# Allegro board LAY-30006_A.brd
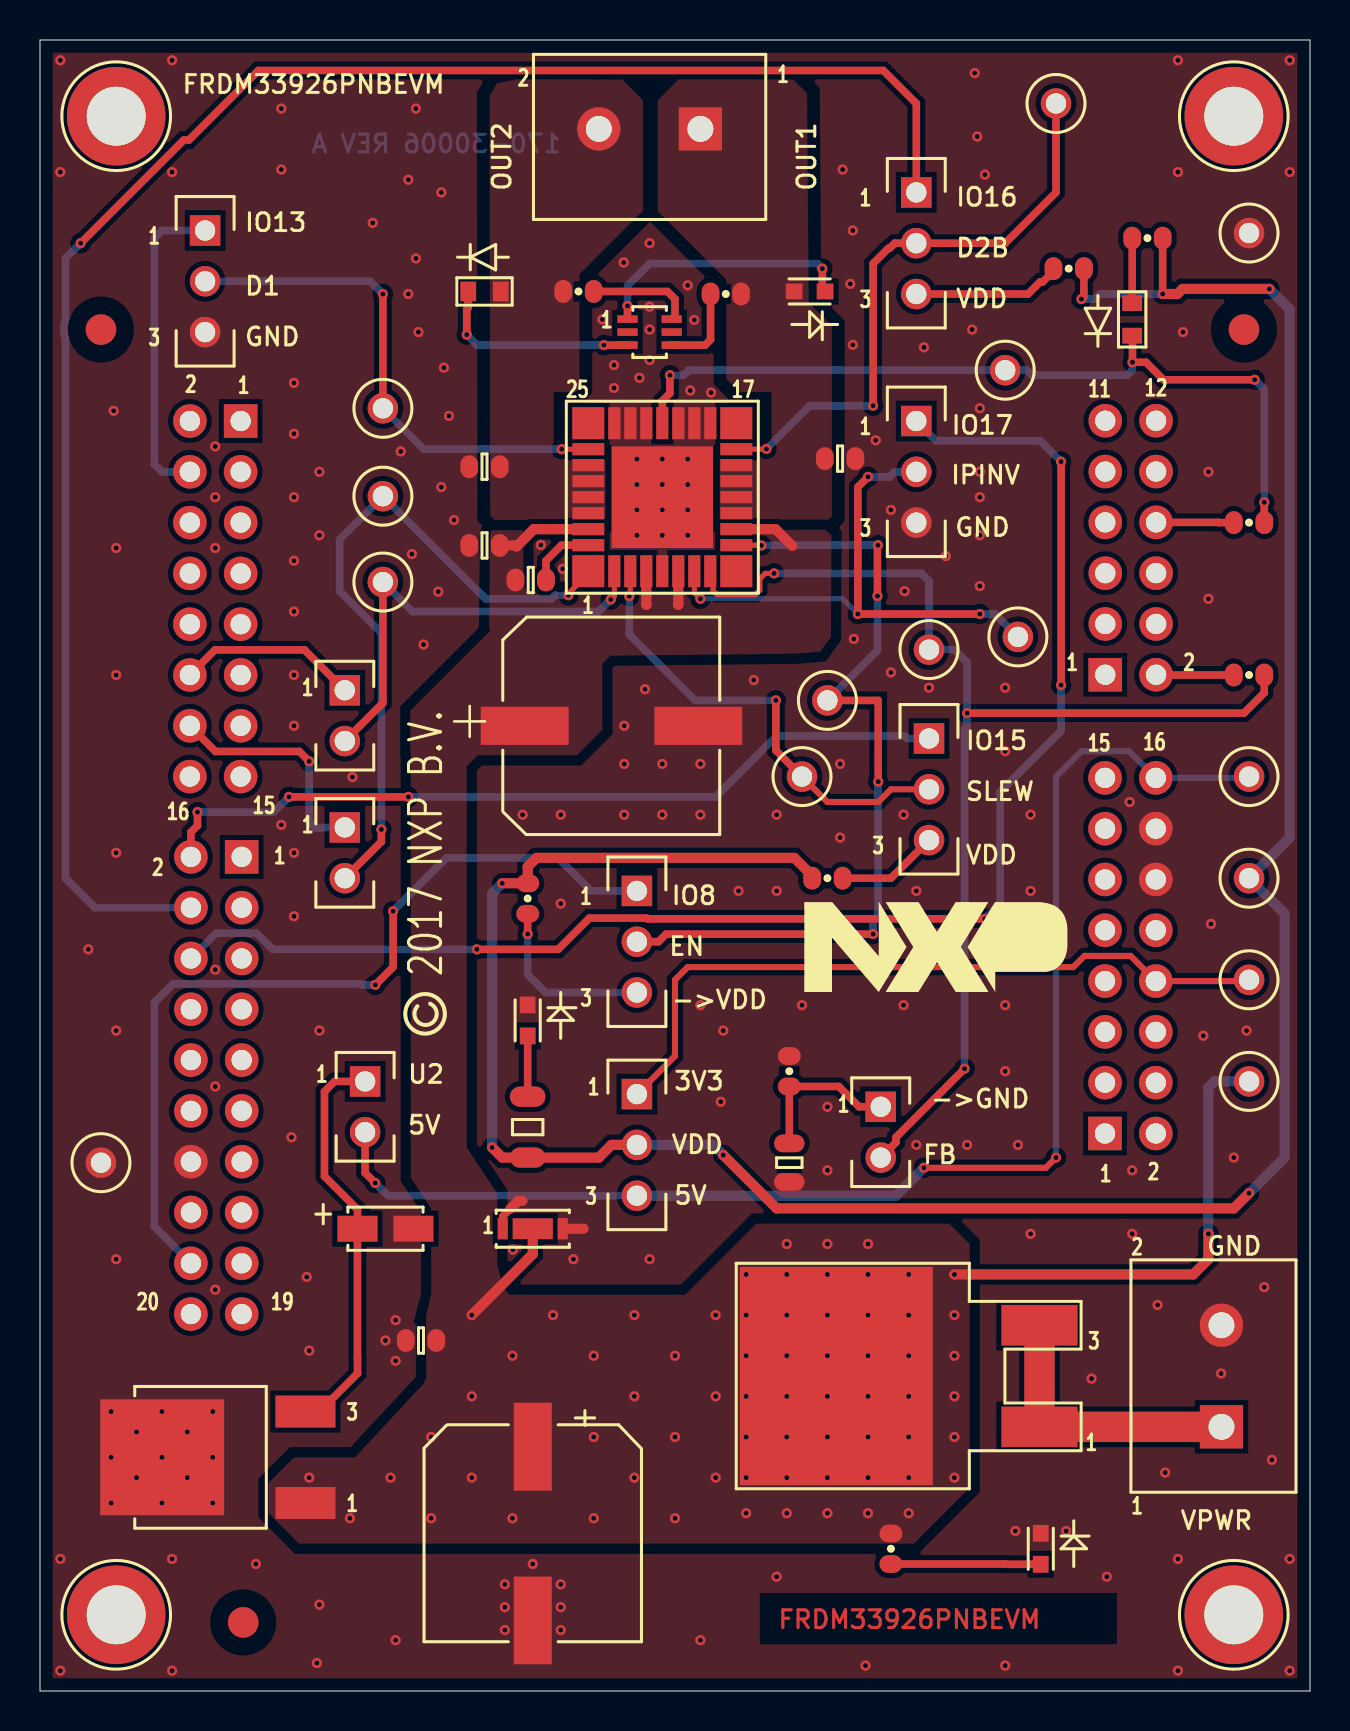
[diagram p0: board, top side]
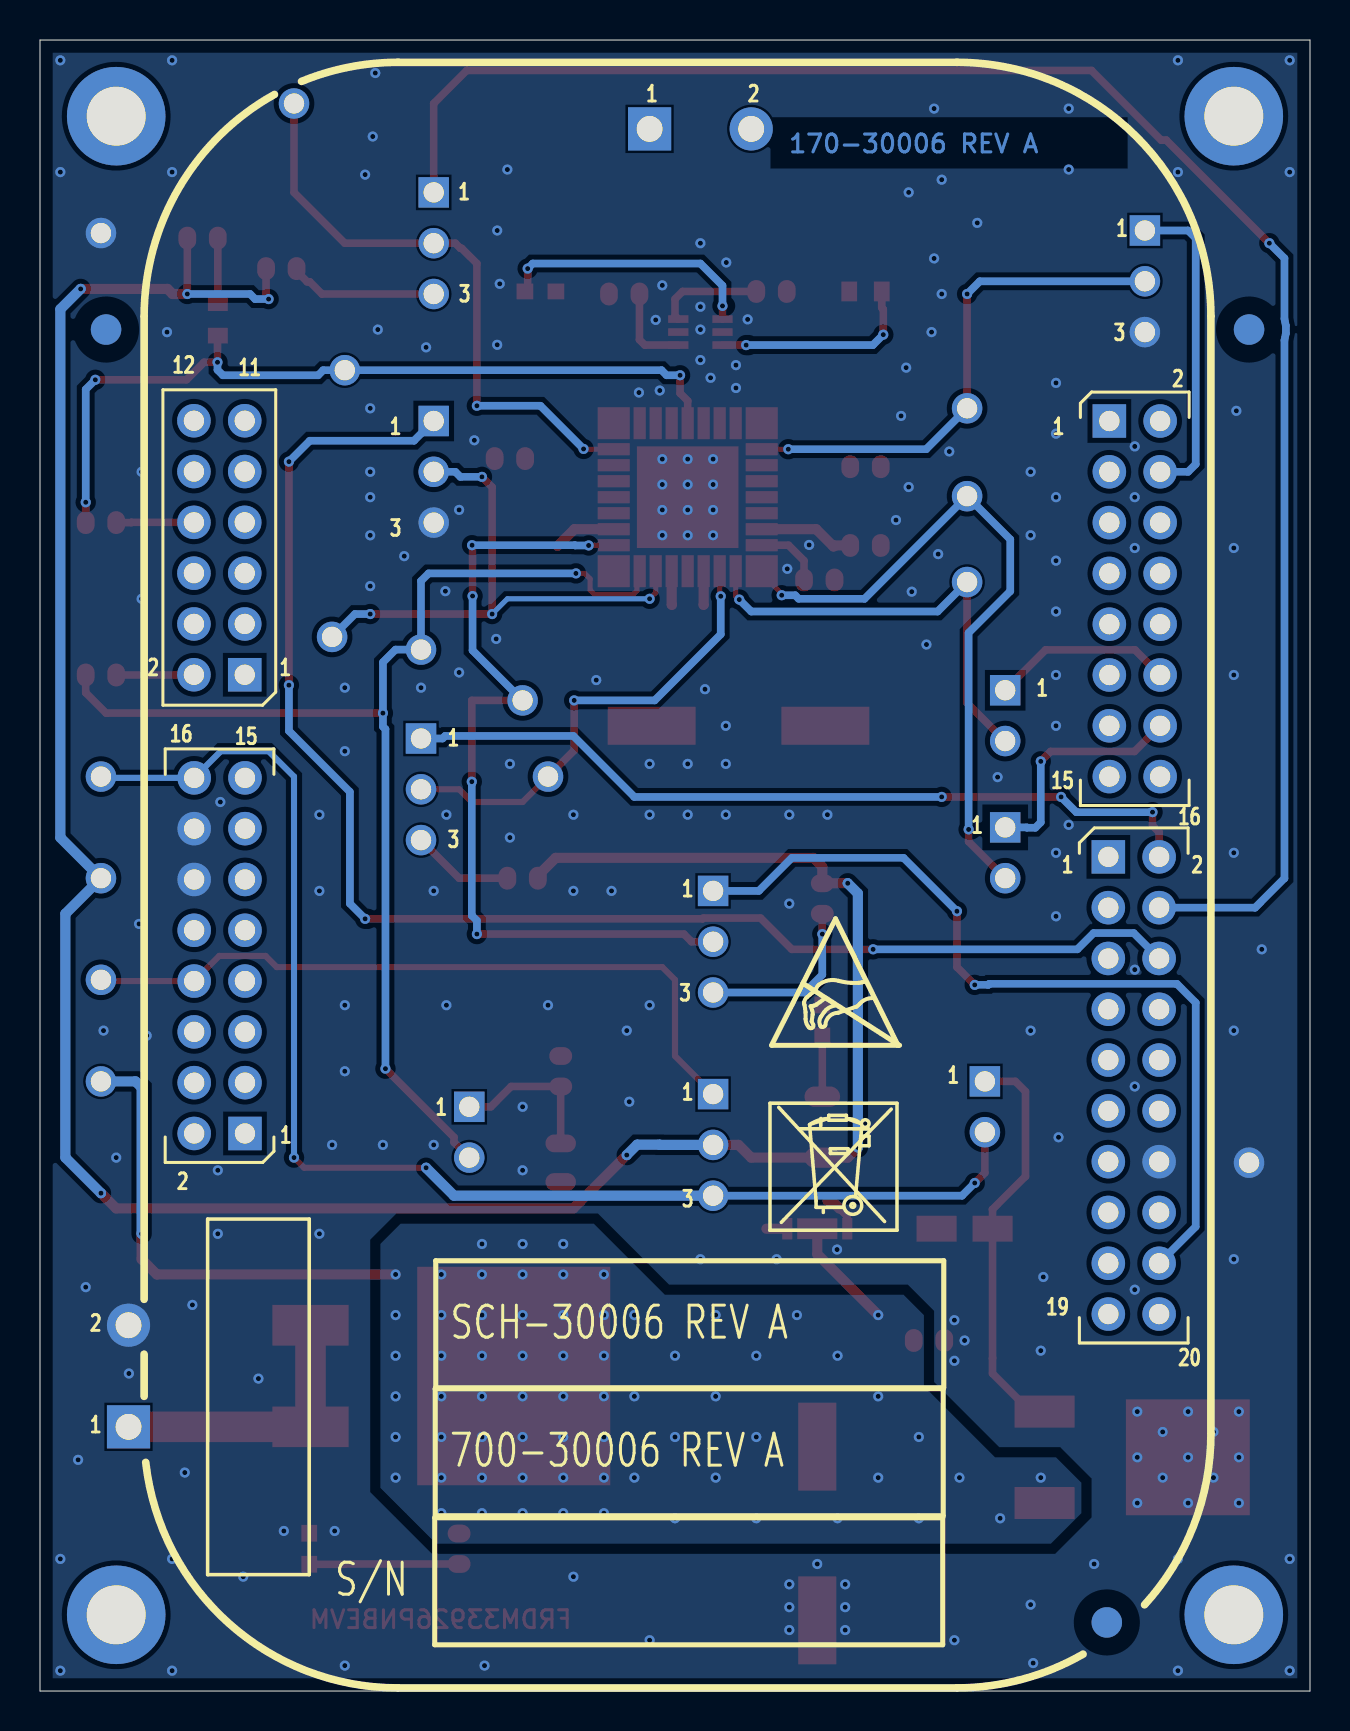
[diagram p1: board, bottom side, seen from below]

Outline 63.5 x 82.55 mm; copper layers: TOP, L2_GND, L3_PWR, BOTTOM. Coordinates in mm from the lower left corner of the outline.
Outline path: 0,82.55 0,0 63.5,0 63.5,82.55 0,82.55

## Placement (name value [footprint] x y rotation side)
BH1  SMTSO-M1.6-2.25ET  [MH194-116T]  3.81 3.81 0 top
BH2  SMTSO-M1.6-2.25ET  [MH194-116T]  59.69 3.81 0 top
BH3  SMTSO-M1.6-2.25ET  [MH194-116T]  59.69 78.74 0 top
BH4  SMTSO-M1.6-2.25ET  [MH194-116T]  3.81 78.74 0 top
C1  47uF  [CCE10_3X10_3]  24.64 7.87 270 top
C2  0.1uF  [CC0603_OV]  19.05 17.53 180 top
C3  10UF  [CASE_A]  17.27 23.11 0 top
C4  47uF  [CCE10_3X10_3]  28.57 48.26 0 top
C5  0.1uF  [CC0603_OV]  22.22 57.28 180 top
C6  0.047UF  [CC0805_OV]  37.47 26.42 270 top
C7  0.033UF  [CC0603_OV]  24.54 55.55 180 top
C8  10nF  [CC0603_OV]  40.01 61.62 0 top
C9  10nF  [CC0603_OV]  22.22 61.21 180 top
D1  MBRB1045T4G  [D2PAK_B]  43.28 15.75 90 top
D2  SPT02-236DDB  [DIODE3_UQFN_SM]  24.64 23.11 0 top
D2B1  TEST POINT BLUE  [TEST_LOOP]  50.8 79.38 0 top
D3  LED_YEL  [LED_0603]  50.04 7.11 90 top
D4  LED GREEN  [LED_0603]  24.38 33.53 90 top
D5  RED  [0603LED]  54.61 68.58 270 top
D6  LED GREEN  [LED_0603]  38.48 69.98 0 top
D7  RED  [0603LED]  22.22 69.98 180 top
D8  BAS70TW-7-F  [SC70-6]  30.48 67.95 270 top
EN1  TEST POINT WHITE  [TEST_LOOP]  39.37 49.53 0 top
FB1  TEST POINT ORANGE  [TEST_LOOP]  44.45 52.07 0 top
GND1  TEST POINT BLACK  [TEST_LOOP]  60.45 72.9 0 top
GND2  TEST POINT BLACK  [TEST_LOOP]  3.05 26.42 0 top
IN1  TEST POINT BLUE  [TEST_LOOP]  17.14 55.45 0 top
IN2  TEST POINT BLUE  [TEST_LOOP]  17.14 59.74 0 top
INPINV1  TEST POINT BLUE  [TEST_LOOP]  48.9 52.71 0 top
J1  HDR_2X8  [HDR208]  10.03 63.5 180 bottom
J2  HDR_2x10  [HDR210]  10.08 41.71 180 bottom
J3  HDR 2X6 TH  [HDR206]  53.26 50.81 0 bottom
J4  HDR_2X8  [HDR208]  53.25 27.88 0 bottom
J5  OSTTC022162  [CON2_TB_5P08_TH_OSTTC]  59.07 13.21 90 top
J6  OSTTC022162  [CON2_TB_5P08_TH_OSTTC]  33.02 78.11 180 top
JP1  HDR 1X2  [HDR102]  16.26 30.48 0 top
JP2  HDR 1X3  [HDR103]  29.84 29.84 0 top
JP3  HDR 1X2  [HDR102]  42.04 29.21 0 top
JP4  HDR 1X3  [HDR103]  8.26 73.03 0 top
JP5  HDR 1X3  [HDR103]  29.84 40.01 0 top
JP6  HDR 1X2  [HDR102]  15.24 50.04 0 top
JP7  HDR 1X2  [HDR102]  15.24 43.18 0 top
JP8  HDR 1X3  [HDR103]  43.82 74.93 0 top
JP9  HDR 1X3  [HDR103]  44.45 47.62 0 top
JP10  HDR 1X3  [HDR103]  43.82 63.5 0 top
NOREF  -  [unnamed]  3.05 68.07 0 top
NOREF#2  -  [#2]  -97.43 -69.06 0 top
NOREF#3  -  [#2]  0 82.55 0 top
NOREF#4  -  [#2]  27.41 55.99 90 top
NOREF#5  -  [#2]  38.23 34.95 0 top
NOREF#6  -  [unnamed]  60.2 68.07 0 top
NOREF#7  -  [unnamed]  10.16 3.43 0 top
NOREF#8  -  [#2]  -361.54 258.75 0 top
NOREF#9  -  [#2]  63.5 0 90 top
NOREF#10  -  [#2]  27.41 55.99 0 top
NOREF#11  -  [#2]  -17.86 -36.68 0 top
NOREF#12  -  [#2]  -402.67 -260.83 0 top
NOREF#13  -  [#2]  3.81 3.81 0 top
NOREF#14  -  [#2]  50.04 5.82 0 top
NOREF#15  -  [#2]  19.28 33.86 90 top
NOREF#16  -  [#2]  116.92 82.58 0 top
NOREF#17  -  [#2]  26.29 22.36 90 top
NOREF#18  -  [#2]  22.99 22.36 0 top
NOREF#19  -  [#2]  23.14 23.11 0 top
NOREF#20  -  [unnamed]  10.16 3.43 180 bottom
NOREF#21  -  [#2]  27 23.04 180 bottom
NOREF#22  -  [unnamed]  3.05 68.07 180 bottom
NOREF#23  -  [#2]  43.71 15.16 180 bottom
NOREF#24  -  [#2]  43.76 2.31 180 bottom
NOREF#25  -  [#2]  26.9 32.28 180 bottom
NOREF#26  -  [unnamed]  60.2 68.07 180 bottom
NOREF#27  -  [#2]  50.04 5.82 90 bottom
NOREF#28  -  [#2]  43.74 8.76 180 bottom
R1  1K  [RC0603_OV]  42.55 7.11 270 top
R2  470  [RC1206_OV]  24.38 28.19 90 top
R3  4.70K  [RC0603_OV]  55.37 72.64 180 top
R4  270  [RC0603_OV]  37.47 30.99 90 top
R5  0  [RC0603_OV]  60.45 58.42 0 top
R6  0  [RC0603_OV]  60.45 50.8 0 top
R7  1K  [RC0603_OV]  24.38 39.62 270 top
R8  10.0K  [RC0603_OV]  26.92 69.98 180 top
R9  10.0K  [RC0603_OV]  34.29 69.85 0 top
R10  1K  [RC0603_OV]  51.44 71.12 180 top
R11  1K  [RC0603_OV]  39.37 40.64 0 top
SF_B1  TEST POINT YELLOW  [TEST_LOOP]  48.26 66.04 0 top
SLEWSEL1  TEST POINT BLUE  [TEST_LOOP]  38.1 45.72 0 top
TP_D1  TEST POINT WHITE  [TEST_LOOP]  17.14 64.14 0 top
U2  MC78M05CDTRKG  [DPAK_CASE_369C-01]  7.39 11.68 90 top
U3  MC33926  [PQFN32_0P8_8X8_SLUG]  31.11 59.69 90 top
UNK3V3  TEST POINT RED  [TEST_LOOP]  60.45 35.56 0 top
UNK5V0  TEST POINT RED  [TEST_LOOP]  60.45 45.72 0 top
VDD1  TEST POINT RED  [TEST_LOOP]  60.45 40.64 0 top
VPWR1  TEST POINT RED  [TEST_LOOP]  60.45 30.48 0 top

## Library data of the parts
BH1-BH4 = MOUNT_HOLE
C1 C3 C4 = CAP_POL
C2 C5-C9 = CAP_NP
D1 = Diode_13A_4C
D2 = DZ_DUAL_CK_A1A2C
D2B1 EN1 FB1 GND1 GND2 IN1 IN2 INPINV1 SF_B1 SLEWSEL1 TP_D1 UNK3V3 UNK5V0 VDD1 VPWR1 = TestLoop
D3-D7 = LED
D8 = BAS70TW
J1 J4 = CONN_HDR_8X2
J2 = CONN_HDR_10X2
J3 = CONN_HDR_6X2
J5 J6 = HDR-1X2
JP1 JP3 JP6 JP7 = CONN_HDR_2X1
JP2 JP4 JP5 JP8-JP10 = CONN_HDR_3X1
R1-R11 = RES
U2 = MC7805
U3 = MC33926

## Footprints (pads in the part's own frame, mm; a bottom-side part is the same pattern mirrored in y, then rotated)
0603LED
  rect 0.787x0.991 smd: A(-0.813,0) C(0.813,0)
CASE_A
  rect 2.007x1.295 smd: 1(-1.4,0) 2(1.4,0)
CC0603_OV
  oval 0.889x1.143 smd: 1(-0.762,0) 2(0.762,0)
CC0805_OV
  oval 0.889x1.524 smd: 1(-0.965,0) 2(0.965,0)
CCE10_3X10_3
  rect 4.394x1.905 smd: 1(-4.343,0) 2(4.343,0)
CON2_TB_5P08_TH_OSTTC
  rect 2.159x2.159 hole 1.295: 1(0,0)
  round 2.159 hole 1.295: 2(5.08,0)
D2PAK_B
  rect 2.032x3.81 smd: 1(-2.54,-6.695) 3(2.54,-6.695)
  rect 10.922x9.652 smd: 4(0,3.465)
DIODE3_UQFN_SM
  rect 0.508x1.067 smd: 1(-1.5,0) 2(1.5,0)
  rect 2.007x1.041 smd: 3(0,0)
DPAK_CASE_369C-01
  rect 1.6x2.997 smd: 1(-2.286,-5.88) 3(2.286,-5.88)
  rect 5.791x6.198 smd: 4(0,1.283)
HDR102
  rect 1.524x1.524 hole 1.016: 1(0,0)
  round 1.524 hole 1.016: 2(0,-2.54)
HDR103
  rect 1.524x1.524 hole 1.016: 1(0,0)
  round 1.524 hole 1.016: 2(0,-2.54) 3(0,-5.08)
HDR206
  rect 1.676x1.676 hole 1.016: 1(0,0)
  round 1.676 hole 1.016: 2(2.54,0) 3(0,-2.54) 4(2.54,-2.54) 5(0,-5.08) 6(2.54,-5.08) 7(0,-7.62) 8(2.54,-7.62) 9(0,-10.16) 10(2.54,-10.16) 11(0,-12.7) 12(2.54,-12.7)
HDR208
  rect 1.676x1.676 hole 1.016: 1(0,0)
  round 1.676 hole 1.016: 2(2.54,0) 3(0,-2.54) 4(2.54,-2.54) 5(0,-5.08) 6(2.54,-5.08) 7(0,-7.62) 8(2.54,-7.62) 9(0,-10.16) 10(2.54,-10.16) 11(0,-12.7) 12(2.54,-12.7) 13(0,-15.24) 14(2.54,-15.24) 15(0,-17.78) 16(2.54,-17.78)
HDR210
  rect 1.676x1.676 hole 1.016: 1(0,0)
  round 1.676 hole 1.016: 2(2.54,0) 3(0,-2.54) 4(2.54,-2.54) 5(0,-5.08) 6(2.54,-5.08) 7(0,-7.62) 8(2.54,-7.62) 9(0,-10.16) 10(2.54,-10.16) 11(0,-12.7) 12(2.54,-12.7) 13(0,-15.24) 14(2.54,-15.24) 15(0,-17.78) 16(2.54,-17.78) 17(0,-20.32) 18(2.54,-20.32) 19(0,-22.86) 20(2.54,-22.86)
LED_0603
  rect 0.838x0.787 smd: A(-0.775,0) C(0.775,0)
MH194-116T
  round 4.928 hole 2.946: 1(0,0)
PQFN32_0P8_8X8_SLUG
  rect 1.6x1.6 smd: 1(-3.7,3.7) 9(-3.7,-3.7) 17(3.7,-3.7) 25(3.7,3.7)
  rect 1.6x0.61 smd: 2(-3.7,2.4) 3(-3.7,1.6) 4(-3.7,0.8) 5(-3.7,0) 6(-3.7,-0.8) 7(-3.7,-1.6) 8(-3.7,-2.4) 18(3.7,-2.4) 19(3.7,-1.6) 20(3.7,-0.8) 21(3.7,0) 22(3.7,0.8) 23(3.7,1.6) 24(3.7,2.4)
  rect 0.61x1.6 smd: 10(-2.4,-3.7) 11(-1.6,-3.7) 12(-0.8,-3.7) 13(0,-3.7) 14(0.8,-3.7) 15(1.6,-3.7) 16(2.4,-3.7) 26(2.4,3.7) 27(1.6,3.7) 28(0.8,3.7) 29(0,3.7) 30(-0.8,3.7) 31(-1.6,3.7) 32(-2.4,3.7)
  rect 5.08x5.08 smd: 33(0,0)
RC0603_OV
  oval 0.889x1.143 smd: 1(-0.762,0) 2(0.762,0)
RC1206_OV
  oval 1.016x1.778 smd: 1(-1.524,0) 2(1.524,0)
SC70-6
  rect 0.381x1.016 smd: 1(-0.65,-1.105) 2(0,-1.105) 3(0.65,-1.105) 4(0.65,1.105) 5(0,1.105) 6(-0.65,1.105)
TEST_LOOP
  round 1.524 hole 1.016: 1(0,0)
unnamed
  round 1.524 smd: (0,0)

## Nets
3V3: J4.8(B4) JP2.1 UNK3V3.1
5V: J4.16(B8) JP1.2 JP2.3 UNK5V0.1
GND_SIGNAL: C1.2 C2.2 C3.2 C4.2 C5.2 C6.2 C8.2 C9.2 D2.1(ANODE1) D2.2(ANODE2) D3.C(CATHODE) D4.C(CATHODE) GND1.1(PIN1) GND2.1(PIN1) J2.14 J4.12(B6) J4.14(B7) J5.2 JP4.3 JP10.3 R4.2 U2.4(GND) U3.5(AGND_1) U3.18(PGND_1) U3.19(PGND_2) U3.20(PGND_3) U3.22(PGND_4) U3.23(PGND_5) U3.24(PGND_6) U3.33(AGND_2)
VBAT: C1.1 C2.1 C4.1 C5.1 C7.2 D1.4(CATHODE) D2.3(CATHODE) R1.1 U2.1(IN) U3.4(VPWR_1) U3.6(VPWR_2) U3.11(VPWR_3) U3.31(VPWR_4) VPWR1.1(PIN1)
VDD: JP2.2 R2.1 R3.1 R7.1 R10.1 R11.1 VDD1.1(PIN1)
AN0: J3.2(B1) R6.1
D1: JP4.2 TP_D1.1(PIN1) U3.26(D1)
D2B: D2B1.1(PIN1) JP8.2 U3.16(D\2\)
EN: EN1.1(PIN1) JP5.2 U3.10(EN)
FB: FB1.1(PIN1) JP3.2 R6.2 U3.8(FB)
IN1: IN1.1(PIN1) JP6.2 U3.2(IN1)
IN2: IN2.1(PIN1) JP7.2 U3.1(IN2)
INPINV: INPINV1.1(PIN1) JP10.2 U3.7(INV)
IO8: J2.18 JP5.1
IO13: J1.4(B2) JP4.1
IO14: J3.8(B4) R5.1
IO15: J2.2 JP9.1
IO16: J2.4 JP8.1
IO17: J2.6 JP10.1
OUT1: C8.1 D6.A(ANODE) J6.1 R9.2 U3.12(OUT1_1) U3.13(OUT1_2) U3.14(OUT1_3) U3.15(OUT1_4)
OUT2: C9.1 D7.A(ANODE) J6.2 R8.2 U3.27(OUT2_1) U3.28(OUT2_2) U3.29(OUT2_3) U3.30(OUT2_4)
PWM1: J1.12(B6) JP6.1
PWM2: J1.14(B7) JP7.1
SF_B: D5.C(CATHODE) R5.2 SF_B1.1(PIN1) U3.21(S\F\)
SLEWSEL: JP9.2 SLEWSEL1.1(PIN1) U3.3(SLEW)
N16404454: D3.A(ANODE) R1.2
N16404466: D1.1(ANODE1) D1.3(ANODE2) J5.1
N16404596: C3.1 JP1.1 U2.3(OUT)
N16404846: JP5.3 R7.2
N16404992: C6.1 JP3.1 R4.1
N16405180: D7.C(CATHODE) D8.3(A3)
N16405200: D6.C(CATHODE) D8.1(A1)
N16405574: D4.A(ANODE) R2.2
N16406148: D8.4(C3) R9.1
N16406152: D8.6(C1) R8.1
N16409368: D5.A(ANODE) R3.2
N16478318: JP8.3 R10.2
N16492232: C7.1 U3.32(CCP)
N16695009: JP9.3 R11.2

Pads without a net: BH1 1; BH2 1; BH3 1; BH4 1; D8 2 5; J1 1 2 3 5 6 7 8 9 10 11 13 15 16; J2 1 3 5 7 8 9 10 11 12 13 15 16 17 19 20; J3 1 3 4 5 6 7 9 10 11 12; J4 1 2 3 4 5 6 7 9 10 11 13 15; U3 9 17 25

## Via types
v1: diameter 0.508, hole 0.254, TOP to BOTTOM, 319 vias

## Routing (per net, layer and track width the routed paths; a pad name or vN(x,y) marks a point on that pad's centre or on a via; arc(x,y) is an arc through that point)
3V3: length 36.2
  TOP w0.305: JP2.1 31.75,31.75 31.75,35.56 32.38,36.2 51.66,36.2 52.22,36.75 54.53,36.75 J4.8 60.39,35.5 UNK3V3.1
5V: length 67.6
  TOP w0.305: v1(44.2,26.16) 50.29,26.16 v1(50.8,26.67)
  TOP w0.381: JP1.2 16.26,25.91 v1(16.76,25.4)
  BOTTOM w0.305: v1(50.8,26.67) 50.8,45.72 52.07,46.99 54.46,46.99 J4.16 59.98,45.66 60.05,45.72 UNK5V0.1
  BOTTOM w0.381: JP2.3 17.4,24.76 v1(16.76,25.4)
  BOTTOM w0.508: JP2.3 42.8,24.76 v1(44.2,26.16)
GND_SIGNAL: length 3
  TOP w0.381: D2.1 23.14,23.73 23.52,24.12
  TOP w0.508: 24.13,24.51 23.92,24.51 23.52,24.12 ; D2.2 27.18,23.11
  vias: v1(1.02,81.53) v1(1.02,75.95) v1(1.02,6.6) v1(1.02,1.02) v1(2.41,37.08) v1(3.56,13.97) v1(3.56,11.68) v1(3.56,9.4) v1(3.68,64.01) v1(3.81,57.15) v1(3.81,50.8) v1(3.81,41.91) v1(3.81,33.02) v1(3.81,21.59) v1(4.83,12.95) v1(4.83,10.67) v1(6.1,13.97) v1(6.1,11.68) v1(6.1,9.4) v1(6.6,81.53) v1(6.6,75.95) v1(6.6,6.6) v1(6.6,1.02) v1(7.37,12.95) v1(7.37,10.67) v1(8.64,13.97) v1(8.64,11.68) v1(8.64,9.4) v1(8.76,62.23) v1(8.76,59.69) v1(8.76,57.15) v1(8.76,36.07) v1(8.76,30.23) v1(8.76,20.07) v1(10.79,6.35) v1(12.07,79.12) v1(12.07,76.07) v1(12.07,43.31) v1(12.57,27.69) v1(12.7,65.41) v1(12.7,62.87) v1(12.7,59.69) v1(12.7,56.52) v1(12.7,53.98) v1(12.7,50.8) v1(12.7,48.26) v1(12.7,41.91) v1(12.7,38.73) v1(13.34,20.7) v1(13.46,17.02) v1(13.84,1.4) v1(13.97,60.96) v1(13.97,57.79) v1(13.97,33.02) v1(13.97,4.32) v1(15.62,45.69) v1(16.64,73.41) v1(17.27,17.53) v1(17.78,18.54) v1(17.78,16.51) v1(17.78,2.54) v1(18.03,61.98) v1(18.41,75.56) v1(18.41,69.85) v1(18.59,56.85) v1(18.8,79.12) v1(18.8,71.63) v1(18.92,67.95) v1(19.18,52.32) v1(19.91,54.97) v1(20.07,74.93) v1(20.07,60.2) v1(20.19,66.17) v1(20.45,63.75) v1(20.7,58.55) v1(23.24,5.33) v1(23.24,4.19) v1(23.24,3.05) v1(23.65,22.07) v1(24.13,43.82) v1(24.64,6.35) v1(25.04,57.3) v1(26.04,43.82) v1(26.04,39.37) v1(26.04,5.33) v1(26.04,4.19) v1(26.04,3.05) v1(26.14,56.11) v1(26.67,21.59) v1(28.12,68.58) v1(28.7,66.29) v1(28.7,65.15) v1(29.18,71.42) v1(29.21,48.26) v1(29.21,46.36) v1(29.21,43.82) v1(29.84,61.59) v1(29.84,60.33) v1(29.84,59.05) v1(29.84,57.79) v1(29.97,65.66) v1(30.25,50.09) v1(30.48,72.39) v1(30.48,69.22) v1(30.48,68.07) v1(30.48,66.55) v1(30.48,21.59) v1(31.11,61.59) v1(31.11,60.33) v1(31.11,59.05) v1(31.11,57.79) v1(31.11,46.36) v1(31.11,43.82) v1(32.38,70.28) v1(32.38,61.59) v1(32.38,60.33) v1(32.38,59.05) v1(32.38,57.79) v1(32.51,65.02) v1(32.72,68.55) v1(33.02,46.36) v1(33.02,43.82) v1(33.02,34.29) v1(33.02,2.54) v1(33.55,64.92) v1(34.04,29.46) v1(34.16,33.02) v1(34.92,40.01) v1(35.69,50.55) v1(36.83,43.82) v1(36.83,40.01) v1(36.83,5.71) v1(38.1,34.29) v1(39.37,29.21) v1(39.37,26.04) v1(40.01,46.36) v1(40.01,42.67) v1(40.13,76.07) v1(40.51,70.36) v1(40.64,73.03) v1(40.64,67.31) v1(40.69,52.6) v1(41.28,1.27) v1(41.78,62.53) v1(42.55,59.05) v1(42.55,50.93) v1(43.23,54.99) v1(43.18,43.82) v1(43.18,34.29) v1(43.82,40.01) v1(43.82,27.3) v1(44.2,67.18) v1(44.45,50.16) v1(45.29,56.74) v1(46.36,27.3) v1(46.61,68.07) v1(46.74,80.9) v1(46.86,77.72) v1(46.99,64.14) v1(46.99,60.96) v1(46.99,59.69) v1(46.99,57.79) v1(46.99,55.25) v1(47.24,75.82) v1(48.26,50.16) v1(48.26,46.99) v1(48.26,34.29) v1(48.26,30.99) v1(48.26,1.27) v1(48.77,8) v1(48.9,27.3) v1(49.53,43.82) v1(49.53,40.01) v1(49.53,22.86) v1(51.31,8) v1(52.58,15.62) v1(53.34,5.71) v1(54.48,44.45) v1(54.61,26.04) v1(54.61,22.86) v1(55.88,19.3) v1(56.26,10.92) v1(56.9,81.53) v1(56.9,75.95) v1(56.9,6.6) v1(56.9,1.02) v1(57.15,67.95) v1(58.17,32.77) v1(58.42,60.96) v1(58.42,54.61) v1(58.55,38.35) v1(59.05,15.88) v1(59.69,26.67) v1(60.33,33.02) v1(61.21,20.19) v1(61.59,11.56) v1(62.48,81.53) v1(62.48,75.95) v1(62.48,6.6) v1(62.48,1.02)
VBAT: length 40.7
  TOP w0.508: 31.9,54.31 31.92,54.32 U3.6 ; U3.31 24.69,58.09 23.83,57.23 23.77,57.28 C5.1 ; v1(21.59,18.8) 24.64,21.84 D2.3 ; 30.33,54.31 30.31,54.32 U3.4 ; v1(45.72,20.83) 57.66,20.83 58.42,21.59 v1(58.42,22.86) ; 37.62,57.25 36.78,58.09 U3.11
  BOTTOM w0.508: v1(58.42,22.86) 58.42,30.18 58.72,30.48 VPWR1.1
  vias: v1(13.46,10.67) v1(15.49,8.64) v1(17.53,10.67) v1(19.56,12.7) v1(19.56,8.64) v1(21.59,14.73) v1(21.59,10.67) v1(23.62,16.76) v1(23.62,8.64) v1(25.65,18.8) v1(27.69,16.76) v1(27.69,12.7) v1(27.69,8.64) v1(29.72,18.8) v1(29.72,14.73) v1(29.72,10.67) v1(31.75,16.76) v1(31.75,12.7) v1(31.75,8.64) v1(33.78,18.8) v1(33.78,14.73) v1(33.78,10.67) v1(35.31,20.83) v1(35.31,18.8) v1(35.31,16.76) v1(35.31,14.73) v1(35.31,12.7) v1(35.31,10.67) v1(35.31,8.89) v1(37.34,22.35) v1(37.34,20.83) v1(37.34,18.8) v1(37.34,16.76) v1(37.34,14.73) v1(37.34,12.7) v1(37.34,10.67) v1(37.34,8.89) v1(39.37,22.35) v1(39.37,20.83) v1(39.37,18.8) v1(39.37,16.76) v1(39.37,14.73) v1(39.37,12.7) v1(39.37,10.67) v1(39.37,8.89) v1(41.4,22.35) v1(41.4,20.83) v1(41.4,18.8) v1(41.4,16.76) v1(41.4,14.73) v1(41.4,12.7) v1(41.4,10.67) v1(41.4,8.89) v1(43.43,20.83) v1(43.43,18.8) v1(43.43,16.76) v1(43.43,14.73) v1(43.43,12.7) v1(43.43,10.67) v1(43.43,8.89) v1(45.72,18.8) v1(45.72,16.76) v1(45.72,14.73) v1(45.72,12.7) v1(45.72,10.67)
VDD: length 132.3
  TOP w0.381: R10.1 52.2,69.72 v1(52.07,69.6) ; v1(56.13,69.85) R3.1
  TOP w0.508: v1(56.13,69.85) 56.87,69.85 57.12,70.1 v1(61.47,70.1) ; JP2.2 28.57,27.3 27.94,26.67 R2.1 23.11,26.67 v1(22.61,27.18) ; R11.1 38.61,40.77 37.72,41.66 24.83,41.66 24.38,41.21 R7.1 v1(23.11,40.39) ; v1(60.45,24.89) 59.69,24.13 36.83,24.13 v1(34.16,26.8)
  BOTTOM w0.381: v1(52.07,69.6) 52.74,69.6 53,69.85 v1(56.13,69.85)
  BOTTOM w0.508: v1(34.16,26.8) 33.64,27.32 32.52,27.32 32.51,27.3 JP2.2 ; v1(60.45,24.89) 62.23,26.67 62.23,38.86 VDD1.1 62.48,42.67 62.48,69.09 v1(61.47,70.1) ; v1(23.11,40.39) 22.61,39.88 v1(22.61,27.18)
AN0: length 4
  TOP w0.254: J3.2 55.77,50.81 55.75,50.8
  TOP w0.381: 55.75,50.8 R6.1
D1: length 26
  TOP w0.254: U3.26 v1(26.09,62.09)
  TOP w0.381: v1(17.14,69.85) TP_D1.1
  BOTTOM w0.381: v1(26.09,62.09) 19.19,62.09 TP_D1.1 ; v1(17.14,69.85) 16.51,70.48 JP4.2
D2B: length 29.9
  TOP w0.254: U3.16 36.31,62.09 v1(36.32,62.1)
  TOP w0.381: v1(41.66,64.26) 41.66,71.37 42.42,72.14 42.48,72.14 42.74,72.39 JP8.2 48.26,72.39 50.8,74.93 D2B1.1
  BOTTOM w0.381: v1(41.66,64.26) 38.48,64.26 v1(36.32,62.1)
EN: length 42.2
  TOP w0.254: U3.10 35.78,57.29 35.79,57.28 v1(36.07,57.28)
  TOP w0.381: v1(41.87,54.75) 41.87,57.26 v1(41.9,57.29) ; JP5.2 30.92,37.47 31.31,37.85 v1(41.66,37.85) ; EN1.1 41.91,49.53 v1(41.91,45.47)
  BOTTOM w0.381: v1(41.87,54.75) 41.87,52.03 EN1.1 ; v1(41.66,37.85) 41.66,38.52 41.91,38.77 v1(41.91,45.47) ; v1(41.9,57.29) 36.75,57.29 36.74,57.28 v1(36.07,57.28)
FB: length 61.2
  TOP w0.254: U3.8 33.66,55.85 33.66,55.02 33.86,54.81 35.76,54.81 35.99,55.04 35.99,55.61 36.26,55.88 v1(36.7,55.88)
  TOP w0.381: v1(46.36,48.9) 60.2,48.9 61.21,49.91 R6.2 ; v1(46.23,31.11) 42.8,27.69 42.8,27.43 JP3.2
  BOTTOM w0.381: v1(46.23,31.11) 46.23,48.09 46.36,48.22 v1(46.36,48.9) 46.36,51.44 45.72,52.07 FB1.1 44.45,55.5 44.07,55.88 v1(36.7,55.88)
IN1: length 22.5
  TOP w0.254: v1(28.54,54.57) 28.71,54.75 U3.2
  TOP w0.381: IN1.1 17.14,49.4 JP6.2
  BOTTOM w0.381: v1(28.54,54.57) 27.94,53.98 18.62,53.98 IN1.1
IN2: length 34.7
  TOP w0.254: U3.1 27.41,55.86 26.42,54.86 v1(26.42,54.79)
  TOP w0.381: v1(17.07,43.08) 17.07,42.47 JP7.2
  BOTTOM w0.381: v1(26.42,54.79) 25.74,54.79 25.57,54.61 22.28,54.61 IN2.1 14.99,57.58 14.99,54.99 17.07,52.91 v1(17.07,43.08)
INPINV: length 27.8
  TOP w0.254: U3.7 32.71,54.92 v1(33.02,54.61)
  TOP w0.381: v1(46.99,53.85) v1(40.89,53.85) 40.89,60.2 v1(41.4,60.71)
  BOTTOM w0.254: v1(40.89,53.85) 40.13,54.61 v1(33.02,54.61)
  BOTTOM w0.381: v1(41.4,60.71) 42.48,60.71 42.74,60.96 JP10.2 ; INPINV1.1 47.75,53.85 v1(46.99,53.85)
IO8: length 43.3
  TOP w0.381: v1(17.65,38.99) 17.65,36.2 v1(16.76,35.31)
  BOTTOM w0.381: v1(17.65,38.99) 20.32,41.66 25.91,41.66 27.56,40.01 JP5.1 ; v1(16.76,35.31) 16.09,35.31 16.04,35.36 6.65,35.36 5.71,34.42 5.71,23.22 J2.18
IO13: length 15.9
  BOTTOM w0.381: JP4.1 6.1,73.03 5.71,72.64 5.71,61.34 6.1,60.96 7.49,60.96
IO14: length 3.9
  TOP w0.381: R5.1 58.93,58.42 58.92,58.43 J3.8
IO15: length 40.6
  TOP w0.381: v1(7.87,43.94) 7.87,43.27 7.54,42.94 J2.2 ; v1(12.45,44.7) v1(18.41,44.7)
  BOTTOM w0.381: v1(18.41,44.7) 33.78,44.7 36.83,47.75 43.24,47.75 43.37,47.62 JP9.1 ; v1(12.45,44.7) 11.68,43.94 v1(7.87,43.94)
IO16: length 89.4
  TOP w0.381: JP8.1 43.82,79.38 42.16,81.03 10.92,81.03 7.44,77.55 7.19,77.55 v1(2.03,72.39)
  BOTTOM w0.381: v1(2.03,72.39) 1.28,71.63 1.28,68.61 1.21,68.25 1.21,67.89 1.28,67.53 1.28,40.63 2.74,39.17 J2.4
IO17: length 73.7
  TOP w0.381: v1(47.24,38.61) 30.37,38.61 30.33,38.65 27.47,38.65 25.91,37.08 v1(21.84,37.08) ; v1(51.05,61.47) v1(51.05,50.29)
  BOTTOM w0.381: JP10.1 44.8,62.51 50.01,62.51 v1(51.05,61.47) ; J2.6 8.81,37.9 10.82,37.9 11.63,37.08 v1(21.84,37.08) ; v1(47.24,38.61) 48.01,39.37 48.01,44.96 51.05,48.01 v1(51.05,50.29)
PWM1: length 9.1
  TOP w0.381: JP6.1 13.22,52.06 8.75,52.06 7.49,50.8
PWM2: length 11.6
  TOP w0.381: 7.49,48.26 8.78,46.98 12.97,46.98 v1(13.46,46.48)
  BOTTOM w0.381: JP7.1 14.16,43.18 14.15,43.16 13.73,43.16 13.46,43.43 v1(13.46,46.48)
SF_B: length 41.5
  TOP w0.381: U3.21 31.11,64.51 31.5,64.89 v1(31.5,65.79) ; v1(60.73,65.56) 56.17,65.56 55.3,66.44 v1(54.63,66.44) 54.63,67.75 D5.C ; R5.2 v1(61.21,59.44)
  BOTTOM w0.381: v1(31.5,65.79) 32.17,65.79 32.42,66.04 SF_B1.1 49.34,66.04 49.59,65.79 54.36,65.79 54.63,66.06 v1(54.63,66.44) ; v1(60.73,65.56) 61.21,65.08 v1(61.21,59.44)
SLEWSEL: length 23.4
  TOP w0.254: U3.3 29.52,54.84 29.46,54.79 v1(29.46,54.74)
  TOP w0.305: SLEWSEL1.1 39.37,44.45 41.91,44.45 42.55,45.09 JP9.2
  TOP w0.381: SLEWSEL1.1 36.79,47.03 v1(36.79,49.53)
  BOTTOM w0.381: v1(29.46,54.74) 29.46,52.83 32.77,49.53 v1(36.79,49.53)
N16404454: length 7.5
  TOP w0.381: R1.2 48.26,6.35 48.27,6.34 D3.A
N16404466: length 14.2
  TOP w1.524: J5.1 D1.1 D1.3
N16404596: length 20.4
  TOP w0.381: U2.3 13.97,13.97 15.88,15.88 15.88,16.64 15.87,16.64 C3.1 15.87,24.08 15.88,24.08 14.22,25.73 14.22,29.97 14.73,30.48 JP1.1
N16404846: length 8.9
  TOP w0.381: v1(24.38,37.85) R7.2
  BOTTOM w0.381: JP5.3 25.27,34.92 24.38,35.81 v1(24.38,37.85)
N16404992: length 7.8
  TOP w0.381: JP3.1 40.96,29.21 39.94,30.23 R4.1 C6.1
N16405180: length 10.4
  TOP w0.381: D7.C 21.41,69.16 21.34,69.09 v1(21.34,67.82) ; D8.3 v1(28.19,67.29)
  BOTTOM w0.381: v1(21.34,67.82) 21.86,67.29 v1(28.19,67.29)
N16405200: length 13.2
  TOP w0.381: v1(39.12,71.12) 39.12,70.12 D6.C ; D8.1 v1(29.38,69.25)
  BOTTOM w0.381: v1(39.12,71.12) 38.86,71.37 30.48,71.37 29.38,70.27 v1(29.38,69.25)
N16405574: length 3
  TOP w0.381: R2.2 D4.A
N16406148: length 4.3
  TOP w0.381: R9.1 33.53,67.56 33.26,67.29 D8.4
N16406152: length 5.3
  TOP w0.381: D8.6 31.75,68.76 31.75,69.6 31.37,69.98 R8.1
N16409368: length 3.3
  TOP w0.381: R3.2 D5.A
N16478318: length 7.5
  TOP w0.381: R10.2 50.67,70.99 50.13,70.45 50.01,70.45 49.4,69.85 JP8.3
N16492232: length 3.4
  TOP w0.381: U3.32 26.07,57.29 25.3,56.52 C7.1
N16695009: length 5.1
  TOP w0.381: JP9.3 42.55,40.64 R11.2

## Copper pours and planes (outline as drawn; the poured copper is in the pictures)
GND_SIGNAL on TOP: 0.64,0.64 0.64,81.91 62.86,81.91 62.86,0.64
GND_SIGNAL on BOTTOM: 0.64,0.64 0.64,81.91 62.86,81.91 62.86,0.64 ; 2 cut-outs
GND_SIGNAL on L2_GND, L3_PWR: 0.64,0.64 0.64,81.91 62.86,81.91 62.86,0.64
VBAT on TOP: 35.81,57.91 35.81,55.04 35.74,54.97 24.46,54.97 24.18,55.25 24.16,57.96 24.1,58.06 22.58,58.06 22.5,57.84 22.45,53.19 22.5,53.14 22.5,53.01 18.52,49.02 18.52,46.99 18.72,46.79 26.85,46.79 28.12,48.06 28.12,51.36 28.52,51.77 37.87,51.87 39.01,51.97 39.55,52.71 39.57,57.79 39.24,58.09 36.12,58.09
VBAT on TOP: 21.84,49.53 19.05,49.53 18.54,49.02 18.54,25.65 19.56,24.13 19.56,19.81 19.3,18.8 20.57,18.54 23.88,18.54 24.13,18.8 23.11,20.32 22.86,21.34 22.86,24.89 21.34,27.18 21.34,46.23 21.84,46.74
VBAT on TOP: 15.75,11.68 12.7,11.68 11.43,10.41 11.43,8.89 12.95,7.37 43.69,7.37 46.48,10.16 46.48,22.35 45.47,23.37 35.81,23.37 32.26,19.81 20.32,19.81 19.3,18.8 19.3,15.62 19.18,15.37
VBAT on BOTTOM: 15.75,11.68 12.7,11.68 11.43,10.41 11.43,8.89 12.95,7.37 43.69,7.37 46.48,10.16 46.48,22.35 45.47,23.37 35.81,23.37 32.26,19.81 20.32,19.81 19.3,18.8 19.3,15.24
VBAT on L2_GND, L3_PWR: 15.75,11.68 12.7,11.68 11.43,10.41 11.43,8.89 12.95,7.37 43.69,7.37 46.48,10.16 46.48,22.35 45.47,23.37 35.81,23.37 32.26,19.81 20.32,19.81 19.3,18.8 19.3,15.75 19.56,15.49
OUT1 on TOP: 33.99,58.57 39.42,58.57 39.6,58.75 39.6,68.25 38.43,69.41 38.35,79.88 37.67,80.57 31.93,80.59 30.89,79.53 30.89,73.99 34.32,70.56 34.32,65.61 34.98,64.95 36.58,64.95 36.58,61.7 34.01,61.7 33.99,61.67
OUT2 on TOP: 28.27,58.55 28.27,61.67 28.24,61.7 25.73,61.7 25.68,61.65 25.68,64.92 25.7,64.95 26.77,64.95 26.97,65.15 26.97,70.84 30.15,74.02 30.15,79.53 29.13,80.57 23.83,80.59 22.86,80.39 22.48,79.76 22.5,58.78 22.73,58.55

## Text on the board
BOTTOM: 170-30006 REV A | 7 OF 10 | SECONDARY SIDE
Board Geometry/Soldermask Bottom: 8 OF 10 | SECONDARY SOLDERMASK
Ref Des/Silkscreen Bottom: 10 OF 10 | SECONDARY SILKSCREEN
User.Comments: 1 OF 1 | TEST PROBE | FRDM BOARD | 1/1 | 1
TOP: FRDM33926PNBEVM | 4 OF 10 | PRIMARY SIDE
Board Geometry/Soldermask Top: 3 OF 10 | PRIMARY SOLDERMASK
Ref Des/Silkscreen Top: FRDM33926PNBEVM | IO13 | D1 | GND | U2 | 5V | EN | IO8 | ->VDD | VDD | 3V3 | FB | ->GND | IPINV | IO17 | IO16 | D2B | IO15 | SLEW | VPWR | OUT2 | OUT1 | 2 OF 10 | PRIMARY SILKSCREEN
L2_GND: 5 OF 10 | GROUND PLANE
L3_PWR: 6 OF 10 | POWER PLANE
DIMENSION: " +/- 10% | PRIMARY DATUM | GRID ORIGIN
BODY_CENTER: 23. MALE HEADERS J1, J2, J3, AND J4 SHOULD BE MOUNTED ON THE BOTTOM LAYER | 16 | 8
PASTEMASK_TOP: 1 OF 10 | PASTEMASK TOP
User.5: 9 OF 10 | SECONDARY PASTEMASK
User.9: J16 | 16 | 20 | 2 | J14 | 15 | 1 | 19 | 8 | U3 | R_OA1 | C_OA1 | 9 | C_OA2 | R_OA2 | R2 | R5 | R4 | R6 | 4 | USB_PWR | Q1 | J1 | FLAG0 | FLAG2 | FLAG1 | G_LS1 | 3 | U1 | C55 | C1 | G_LS2 | EXT2 | EXT1 | VBAT_SELECT | C56 | DBG | SEL | J2 | EXT | VCCIO | J6 | CLK_SEL | 5V | 3V3 | J5 | Q3 | INT | C35 | R13 | 64 | U4 | L1 | C14 | SH17 | SH12 | C29 | 11 | 12 | J15 | J17 | R7 | VSUPP | TP11 | TP10 | TP12 | TP8 | TP3 | RESETB | VCCP | DRVEN | IRQB | C5 | DGND | C6 | TP2 | TP13 | TP14 | TP15 | TP16 | C7 | +5V | MISO | MOSI | SCLK | CSB | C4 | R1 | D1 | TP5 | TP6 | TP38 | GND | VBAT | VSENSEP1 | TP41 | C | A | VSENSEN1 | R21 | TP44 | D2 | TP4 | TP9 | CLK | TP26 | D8 | D3 | D6 | D5 | D7 | C39 | C40 | C41 | C42 | C64 | MODEL-28476_R2 | +
User.16: 08-16-17 | W.A | A | FINAL RELEASE
User.21: FIGURE | SIZE | 10.0 | 40.0 | 51.0 | 116.0 | DRILL CHART: TOP to BOTTOM | ALL UNITS ARE IN MILS | TOLERANCE | +0.0/-10.0 | +3.0/-3.0 | +3.15/-0.0 | PLATED | QTY | 319 | 105 | 4
